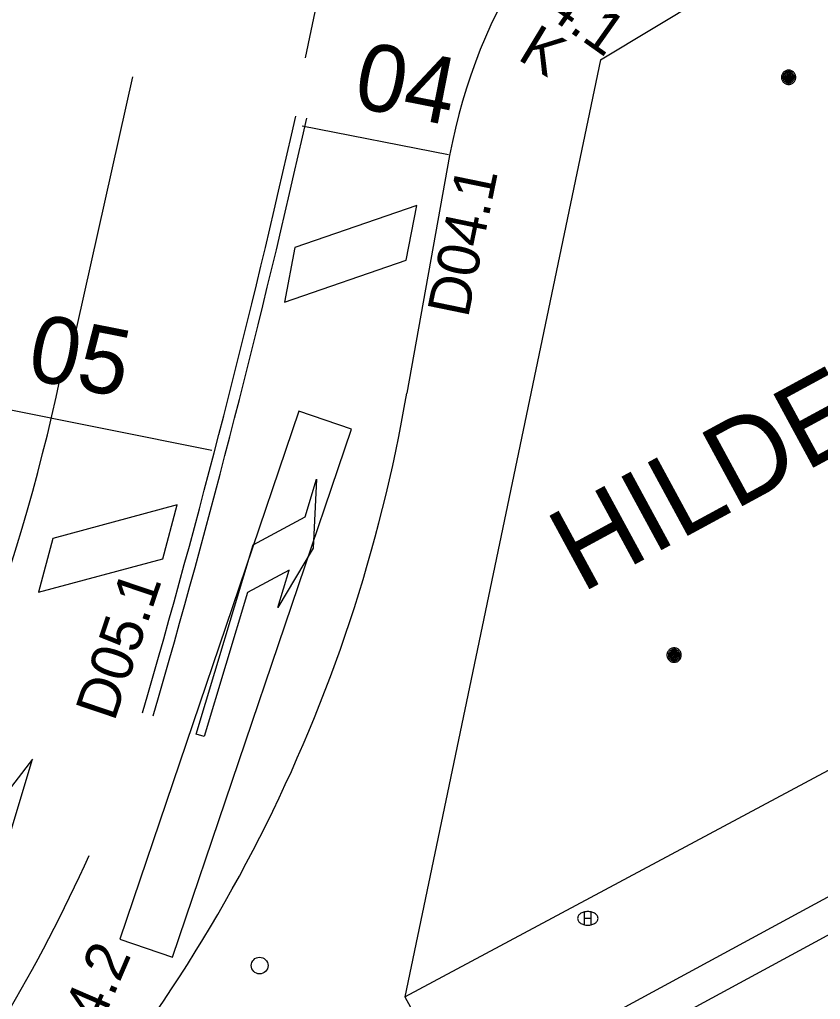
# Model space of a CAD drawing. Extents: x 81065 to 81486, y 452384 to 452681.
# Drawn here: x 81225.4 to 81239.76, y 452493.67 to 452511.24 of the extents above; entities that cross this region are included whole.
import ezdxf

# ---------------------------------------------------------------- set-up
doc = ezdxf.new("R2010")
doc.units = 0
for name, color, linetype in [('B-BH-AL-TOPOGRAFIE_STRAATNAAM-S', 7, 'Continuous'), ('B-BH-GR-BOOM-S', 7, 'Continuous'), ('B-BH-IE-MEUBILAIR_WEGMEUBILAIR_PAAL-S', 7, 'Continuous'), ('B-BH-VH-KANTOPSLUITING-GV', 7, 'Continuous'), ('B-BH-VW-HALTEPAAL-S', 7, 'Continuous'), ('B-SB-OG-WEG_SPOOR_TRAM-G', 7, 'Continuous'), ('B-WE-VW-MARKERING_DWARS_STOPSTREEP_030-G', 7, 'Continuous'), ('B-WE-VW-MARKERING_LANGS_STREEP_11_010-G', 7, 'Continuous'), ('B-WE-VW-MARKERING_LANGS_STREEP_13_010-G', 7, 'Continuous'), ('B-WE-VW-MARKERING_LANGS_STREEP_13_030-G', 7, 'Continuous'), ('B-WE-VW-MARKERING_LANGS_STREEP_DOORGETROKKEN_010-G', 7, 'Continuous'), ('B-WE-VW-MARKERING_PIJL-S', 7, 'Continuous'), ('N-OI-KL-VRI_LUS_DETECTIE-G', 7, 'Continuous'), ('N-OI-KL-VRI_LUS_DETECTIE-T18', 7, 'Continuous'), ('N-WE-VW-VRI_ARMATUUR-S', 7, 'Continuous'), ('N-WE-VW-VRI_ARMATUUR-T18', 7, 'Continuous'), ('N-WE-VW-VRI_RICHTINGNUMMER-T25', 7, 'Continuous')]:
    doc.layers.add(name, color=color, linetype=linetype)

msp = doc.modelspace()

# ---------------------------------------------------------------- linework, layer by layer
at = {"layer": 'B-BH-GR-BOOM-S'}
for points in [[(81239.065, 452510.205), (81239.066, 452510.191), (81239.068, 452510.178), (81239.071, 452510.165), (81239.076, 452510.153), (81239.082, 452510.141), (81239.09, 452510.129), (81239.098, 452510.119), (81239.108, 452510.109), (81239.118, 452510.101), (81239.13, 452510.093), (81239.142, 452510.087), (81239.154, 452510.082), (81239.167, 452510.079), (81239.18, 452510.077), (81239.194, 452510.076), (81239.207, 452510.077), (81239.221, 452510.079), (81239.234, 452510.082), (81239.246, 452510.087), (81239.258, 452510.093), (81239.27, 452510.101), (81239.28, 452510.109), (81239.29, 452510.119), (81239.298, 452510.129), (81239.306, 452510.141), (81239.312, 452510.153), (81239.316, 452510.165), (81239.32, 452510.178), (81239.322, 452510.191), (81239.323, 452510.205), (81239.322, 452510.218), (81239.32, 452510.232), (81239.316, 452510.245), (81239.312, 452510.257), (81239.306, 452510.269), (81239.298, 452510.281), (81239.29, 452510.291), (81239.28, 452510.301), (81239.27, 452510.309), (81239.258, 452510.317), (81239.246, 452510.323), (81239.234, 452510.327), (81239.221, 452510.331), (81239.207, 452510.333), (81239.194, 452510.334), (81239.18, 452510.333), (81239.167, 452510.331), (81239.154, 452510.327), (81239.142, 452510.323), (81239.13, 452510.317), (81239.118, 452510.309), (81239.108, 452510.301), (81239.098, 452510.291), (81239.09, 452510.281), (81239.082, 452510.269), (81239.076, 452510.257), (81239.071, 452510.245), (81239.068, 452510.232), (81239.066, 452510.218), (81239.065, 452510.205)], [(81239.09, 452510.205), (81239.09, 452510.194), (81239.092, 452510.183), (81239.095, 452510.173), (81239.099, 452510.162), (81239.103, 452510.153), (81239.109, 452510.144), (81239.116, 452510.135), (81239.124, 452510.127), (81239.133, 452510.12), (81239.142, 452510.114), (81239.151, 452510.11), (81239.162, 452510.106), (81239.172, 452510.103), (81239.183, 452510.101), (81239.194, 452510.101), (81239.205, 452510.101), (81239.216, 452510.103), (81239.226, 452510.106), (81239.236, 452510.11), (81239.246, 452510.114), (81239.255, 452510.12), (81239.264, 452510.127), (81239.272, 452510.135), (81239.278, 452510.144), (81239.284, 452510.153), (81239.289, 452510.162), (81239.293, 452510.173), (81239.296, 452510.183), (81239.298, 452510.194), (81239.298, 452510.205), (81239.298, 452510.216), (81239.296, 452510.227), (81239.293, 452510.237), (81239.289, 452510.247), (81239.284, 452510.257), (81239.278, 452510.266), (81239.272, 452510.275), (81239.264, 452510.283), (81239.255, 452510.289), (81239.246, 452510.295), (81239.236, 452510.3), (81239.226, 452510.304), (81239.216, 452510.307), (81239.205, 452510.309), (81239.194, 452510.309), (81239.183, 452510.309), (81239.172, 452510.307), (81239.162, 452510.304), (81239.151, 452510.3), (81239.142, 452510.295), (81239.133, 452510.289), (81239.124, 452510.283), (81239.116, 452510.275), (81239.109, 452510.266), (81239.103, 452510.257), (81239.099, 452510.247), (81239.095, 452510.237), (81239.092, 452510.227), (81239.09, 452510.216), (81239.09, 452510.205)], [(81239.112, 452510.205), (81239.113, 452510.196), (81239.114, 452510.188), (81239.116, 452510.18), (81239.119, 452510.172), (81239.123, 452510.164), (81239.128, 452510.157), (81239.133, 452510.15), (81239.139, 452510.144), (81239.146, 452510.139), (81239.153, 452510.134), (81239.161, 452510.13), (81239.169, 452510.127), (81239.177, 452510.125), (81239.185, 452510.124), (81239.194, 452510.123), (81239.202, 452510.124), (81239.211, 452510.125), (81239.219, 452510.127), (81239.227, 452510.13), (81239.235, 452510.134), (81239.242, 452510.139), (81239.249, 452510.144), (81239.255, 452510.15), (81239.26, 452510.157), (81239.265, 452510.164), (81239.268, 452510.172), (81239.272, 452510.18), (81239.274, 452510.188), (81239.275, 452510.196), (81239.276, 452510.205), (81239.275, 452510.213), (81239.274, 452510.222), (81239.272, 452510.23), (81239.268, 452510.238), (81239.265, 452510.246), (81239.26, 452510.253), (81239.255, 452510.26), (81239.249, 452510.266), (81239.242, 452510.271), (81239.235, 452510.276), (81239.227, 452510.279), (81239.219, 452510.283), (81239.211, 452510.285), (81239.202, 452510.286), (81239.194, 452510.287), (81239.185, 452510.286), (81239.177, 452510.285), (81239.169, 452510.283), (81239.161, 452510.279), (81239.153, 452510.276), (81239.146, 452510.271), (81239.139, 452510.266), (81239.133, 452510.26), (81239.128, 452510.253), (81239.123, 452510.246), (81239.119, 452510.238), (81239.116, 452510.23), (81239.114, 452510.222), (81239.113, 452510.213), (81239.112, 452510.205)], [(81239.135, 452510.205), (81239.136, 452510.199), (81239.137, 452510.193), (81239.138, 452510.187), (81239.14, 452510.181), (81239.143, 452510.176), (81239.147, 452510.17), (81239.15, 452510.166), (81239.155, 452510.161), (81239.159, 452510.158), (81239.165, 452510.154), (81239.17, 452510.151), (81239.176, 452510.149), (81239.182, 452510.148), (81239.188, 452510.147), (81239.194, 452510.146), (81239.2, 452510.147), (81239.206, 452510.148), (81239.212, 452510.149), (81239.218, 452510.151), (81239.223, 452510.154), (81239.228, 452510.158), (81239.233, 452510.161), (81239.238, 452510.166), (81239.241, 452510.17), (81239.245, 452510.176), (81239.248, 452510.181), (81239.25, 452510.187), (81239.251, 452510.193), (81239.252, 452510.199), (81239.253, 452510.205), (81239.252, 452510.211), (81239.251, 452510.217), (81239.25, 452510.223), (81239.248, 452510.229), (81239.245, 452510.234), (81239.241, 452510.239), (81239.238, 452510.244), (81239.233, 452510.249), (81239.228, 452510.252), (81239.223, 452510.256), (81239.218, 452510.259), (81239.212, 452510.261), (81239.206, 452510.262), (81239.2, 452510.263), (81239.194, 452510.264), (81239.188, 452510.263), (81239.182, 452510.262), (81239.176, 452510.261), (81239.17, 452510.259), (81239.165, 452510.256), (81239.159, 452510.252), (81239.155, 452510.249), (81239.15, 452510.244), (81239.147, 452510.239), (81239.143, 452510.234), (81239.14, 452510.229), (81239.138, 452510.223), (81239.137, 452510.217), (81239.136, 452510.211), (81239.135, 452510.205)], [(81239.158, 452510.205), (81239.158, 452510.201), (81239.159, 452510.198), (81239.16, 452510.194), (81239.161, 452510.19), (81239.163, 452510.187), (81239.165, 452510.184), (81239.167, 452510.181), (81239.17, 452510.178), (81239.173, 452510.176), (81239.176, 452510.174), (81239.179, 452510.172), (81239.183, 452510.171), (81239.187, 452510.17), (81239.19, 452510.169), (81239.194, 452510.169), (81239.198, 452510.169), (81239.201, 452510.17), (81239.205, 452510.171), (81239.209, 452510.172), (81239.212, 452510.174), (81239.215, 452510.176), (81239.218, 452510.178), (81239.22, 452510.181), (81239.223, 452510.184), (81239.225, 452510.187), (81239.227, 452510.19), (81239.228, 452510.194), (81239.229, 452510.198), (81239.23, 452510.201), (81239.23, 452510.205), (81239.23, 452510.209), (81239.229, 452510.212), (81239.228, 452510.216), (81239.227, 452510.22), (81239.225, 452510.223), (81239.223, 452510.226), (81239.22, 452510.229), (81239.218, 452510.231), (81239.215, 452510.234), (81239.212, 452510.236), (81239.209, 452510.238), (81239.205, 452510.239), (81239.201, 452510.24), (81239.198, 452510.241), (81239.194, 452510.241), (81239.19, 452510.241), (81239.187, 452510.24), (81239.183, 452510.239), (81239.179, 452510.238), (81239.176, 452510.236), (81239.173, 452510.234), (81239.17, 452510.231), (81239.167, 452510.229), (81239.165, 452510.226), (81239.163, 452510.223), (81239.161, 452510.22), (81239.16, 452510.216), (81239.159, 452510.212), (81239.158, 452510.209), (81239.158, 452510.205)], [(81239.181, 452510.205), (81239.181, 452510.204), (81239.181, 452510.202), (81239.182, 452510.201), (81239.182, 452510.2), (81239.183, 452510.199), (81239.184, 452510.197), (81239.184, 452510.196), (81239.185, 452510.195), (81239.186, 452510.195), (81239.188, 452510.194), (81239.189, 452510.193), (81239.19, 452510.193), (81239.191, 452510.192), (81239.193, 452510.192), (81239.194, 452510.192), (81239.195, 452510.192), (81239.197, 452510.192), (81239.198, 452510.193), (81239.199, 452510.193), (81239.2, 452510.194), (81239.202, 452510.195), (81239.203, 452510.195), (81239.204, 452510.196), (81239.204, 452510.197), (81239.205, 452510.199), (81239.206, 452510.2), (81239.206, 452510.201), (81239.207, 452510.202), (81239.207, 452510.204), (81239.207, 452510.205), (81239.207, 452510.206), (81239.207, 452510.208), (81239.206, 452510.209), (81239.206, 452510.21), (81239.205, 452510.211), (81239.204, 452510.213), (81239.204, 452510.214), (81239.203, 452510.215), (81239.202, 452510.215), (81239.2, 452510.216), (81239.199, 452510.217), (81239.198, 452510.217), (81239.197, 452510.218), (81239.195, 452510.218), (81239.194, 452510.218), (81239.193, 452510.218), (81239.191, 452510.218), (81239.19, 452510.217), (81239.189, 452510.217), (81239.188, 452510.216), (81239.186, 452510.215), (81239.185, 452510.215), (81239.184, 452510.214), (81239.184, 452510.213), (81239.183, 452510.211), (81239.182, 452510.21), (81239.182, 452510.209), (81239.181, 452510.208), (81239.181, 452510.206), (81239.181, 452510.205)], [(81237.011, 452499.841), (81237.012, 452499.827), (81237.014, 452499.814), (81237.017, 452499.801), (81237.022, 452499.789), (81237.028, 452499.777), (81237.036, 452499.765), (81237.044, 452499.755), (81237.054, 452499.745), (81237.064, 452499.737), (81237.076, 452499.729), (81237.088, 452499.723), (81237.1, 452499.718), (81237.113, 452499.715), (81237.126, 452499.713), (81237.14, 452499.712), (81237.153, 452499.713), (81237.167, 452499.715), (81237.18, 452499.718), (81237.192, 452499.723), (81237.204, 452499.729), (81237.216, 452499.737), (81237.226, 452499.745), (81237.236, 452499.755), (81237.244, 452499.765), (81237.252, 452499.777), (81237.258, 452499.789), (81237.262, 452499.801), (81237.266, 452499.814), (81237.268, 452499.827), (81237.269, 452499.841), (81237.268, 452499.854), (81237.266, 452499.868), (81237.262, 452499.881), (81237.258, 452499.893), (81237.252, 452499.905), (81237.244, 452499.917), (81237.236, 452499.927), (81237.226, 452499.937), (81237.216, 452499.945), (81237.204, 452499.953), (81237.192, 452499.959), (81237.18, 452499.963), (81237.167, 452499.967), (81237.153, 452499.969), (81237.14, 452499.97), (81237.126, 452499.969), (81237.113, 452499.967), (81237.1, 452499.963), (81237.088, 452499.959), (81237.076, 452499.953), (81237.064, 452499.945), (81237.054, 452499.937), (81237.044, 452499.927), (81237.036, 452499.917), (81237.028, 452499.905), (81237.022, 452499.893), (81237.017, 452499.881), (81237.014, 452499.868), (81237.012, 452499.854), (81237.011, 452499.841)], [(81237.036, 452499.841), (81237.036, 452499.83), (81237.038, 452499.819), (81237.041, 452499.809), (81237.045, 452499.798), (81237.049, 452499.789), (81237.055, 452499.78), (81237.062, 452499.771), (81237.07, 452499.763), (81237.079, 452499.756), (81237.088, 452499.75), (81237.097, 452499.746), (81237.108, 452499.742), (81237.118, 452499.739), (81237.129, 452499.737), (81237.14, 452499.737), (81237.151, 452499.737), (81237.162, 452499.739), (81237.172, 452499.742), (81237.182, 452499.746), (81237.192, 452499.75), (81237.201, 452499.756), (81237.21, 452499.763), (81237.218, 452499.771), (81237.224, 452499.78), (81237.23, 452499.789), (81237.235, 452499.798), (81237.239, 452499.809), (81237.242, 452499.819), (81237.244, 452499.83), (81237.244, 452499.841), (81237.244, 452499.852), (81237.242, 452499.863), (81237.239, 452499.873), (81237.235, 452499.883), (81237.23, 452499.893), (81237.224, 452499.902), (81237.218, 452499.911), (81237.21, 452499.919), (81237.201, 452499.925), (81237.192, 452499.931), (81237.182, 452499.936), (81237.172, 452499.94), (81237.162, 452499.943), (81237.151, 452499.945), (81237.14, 452499.945), (81237.129, 452499.945), (81237.118, 452499.943), (81237.108, 452499.94), (81237.097, 452499.936), (81237.088, 452499.931), (81237.079, 452499.925), (81237.07, 452499.919), (81237.062, 452499.911), (81237.055, 452499.902), (81237.049, 452499.893), (81237.045, 452499.883), (81237.041, 452499.873), (81237.038, 452499.863), (81237.036, 452499.852), (81237.036, 452499.841)], [(81237.058, 452499.841), (81237.059, 452499.832), (81237.06, 452499.824), (81237.062, 452499.816), (81237.065, 452499.808), (81237.069, 452499.8), (81237.074, 452499.793), (81237.079, 452499.786), (81237.085, 452499.78), (81237.092, 452499.775), (81237.099, 452499.77), (81237.107, 452499.766), (81237.115, 452499.763), (81237.123, 452499.761), (81237.131, 452499.76), (81237.14, 452499.759), (81237.148, 452499.76), (81237.157, 452499.761), (81237.165, 452499.763), (81237.173, 452499.766), (81237.181, 452499.77), (81237.188, 452499.775), (81237.195, 452499.78), (81237.201, 452499.786), (81237.206, 452499.793), (81237.211, 452499.8), (81237.214, 452499.808), (81237.218, 452499.816), (81237.22, 452499.824), (81237.221, 452499.832), (81237.222, 452499.841), (81237.221, 452499.849), (81237.22, 452499.858), (81237.218, 452499.866), (81237.214, 452499.874), (81237.211, 452499.882), (81237.206, 452499.889), (81237.201, 452499.896), (81237.195, 452499.902), (81237.188, 452499.907), (81237.181, 452499.912), (81237.173, 452499.915), (81237.165, 452499.919), (81237.157, 452499.921), (81237.148, 452499.922), (81237.14, 452499.923), (81237.131, 452499.922), (81237.123, 452499.921), (81237.115, 452499.919), (81237.107, 452499.915), (81237.099, 452499.912), (81237.092, 452499.907), (81237.085, 452499.902), (81237.079, 452499.896), (81237.074, 452499.889), (81237.069, 452499.882), (81237.065, 452499.874), (81237.062, 452499.866), (81237.06, 452499.858), (81237.059, 452499.849), (81237.058, 452499.841)], [(81237.081, 452499.841), (81237.082, 452499.835), (81237.083, 452499.829), (81237.084, 452499.823), (81237.086, 452499.817), (81237.089, 452499.812), (81237.093, 452499.806), (81237.096, 452499.802), (81237.101, 452499.797), (81237.105, 452499.794), (81237.111, 452499.79), (81237.116, 452499.787), (81237.122, 452499.785), (81237.128, 452499.784), (81237.134, 452499.783), (81237.14, 452499.782), (81237.146, 452499.783), (81237.152, 452499.784), (81237.158, 452499.785), (81237.164, 452499.787), (81237.169, 452499.79), (81237.174, 452499.794), (81237.179, 452499.797), (81237.184, 452499.802), (81237.187, 452499.806), (81237.191, 452499.812), (81237.194, 452499.817), (81237.196, 452499.823), (81237.197, 452499.829), (81237.198, 452499.835), (81237.199, 452499.841), (81237.198, 452499.847), (81237.197, 452499.853), (81237.196, 452499.859), (81237.194, 452499.865), (81237.191, 452499.87), (81237.187, 452499.875), (81237.184, 452499.88), (81237.179, 452499.885), (81237.174, 452499.888), (81237.169, 452499.892), (81237.164, 452499.895), (81237.158, 452499.897), (81237.152, 452499.898), (81237.146, 452499.899), (81237.14, 452499.9), (81237.134, 452499.899), (81237.128, 452499.898), (81237.122, 452499.897), (81237.116, 452499.895), (81237.111, 452499.892), (81237.105, 452499.888), (81237.101, 452499.885), (81237.096, 452499.88), (81237.093, 452499.875), (81237.089, 452499.87), (81237.086, 452499.865), (81237.084, 452499.859), (81237.083, 452499.853), (81237.082, 452499.847), (81237.081, 452499.841)], [(81237.104, 452499.841), (81237.104, 452499.837), (81237.105, 452499.834), (81237.106, 452499.83), (81237.107, 452499.826), (81237.109, 452499.823), (81237.111, 452499.82), (81237.113, 452499.817), (81237.116, 452499.814), (81237.119, 452499.812), (81237.122, 452499.81), (81237.125, 452499.808), (81237.129, 452499.807), (81237.133, 452499.806), (81237.136, 452499.805), (81237.14, 452499.805), (81237.144, 452499.805), (81237.147, 452499.806), (81237.151, 452499.807), (81237.155, 452499.808), (81237.158, 452499.81), (81237.161, 452499.812), (81237.164, 452499.814), (81237.166, 452499.817), (81237.169, 452499.82), (81237.171, 452499.823), (81237.173, 452499.826), (81237.174, 452499.83), (81237.175, 452499.834), (81237.176, 452499.837), (81237.176, 452499.841), (81237.176, 452499.845), (81237.175, 452499.848), (81237.174, 452499.852), (81237.173, 452499.856), (81237.171, 452499.859), (81237.169, 452499.862), (81237.166, 452499.865), (81237.164, 452499.867), (81237.161, 452499.87), (81237.158, 452499.872), (81237.155, 452499.874), (81237.151, 452499.875), (81237.147, 452499.876), (81237.144, 452499.877), (81237.14, 452499.877), (81237.136, 452499.877), (81237.133, 452499.876), (81237.129, 452499.875), (81237.125, 452499.874), (81237.122, 452499.872), (81237.119, 452499.87), (81237.116, 452499.867), (81237.113, 452499.865), (81237.111, 452499.862), (81237.109, 452499.859), (81237.107, 452499.856), (81237.106, 452499.852), (81237.105, 452499.848), (81237.104, 452499.845), (81237.104, 452499.841)], [(81237.127, 452499.841), (81237.127, 452499.84), (81237.127, 452499.838), (81237.128, 452499.837), (81237.128, 452499.836), (81237.129, 452499.835), (81237.13, 452499.833), (81237.13, 452499.832), (81237.131, 452499.831), (81237.132, 452499.831), (81237.134, 452499.83), (81237.135, 452499.829), (81237.136, 452499.829), (81237.137, 452499.828), (81237.139, 452499.828), (81237.14, 452499.828), (81237.141, 452499.828), (81237.143, 452499.828), (81237.144, 452499.829), (81237.145, 452499.829), (81237.146, 452499.83), (81237.148, 452499.831), (81237.149, 452499.831), (81237.15, 452499.832), (81237.15, 452499.833), (81237.151, 452499.835), (81237.152, 452499.836), (81237.152, 452499.837), (81237.153, 452499.838), (81237.153, 452499.84), (81237.153, 452499.841), (81237.153, 452499.842), (81237.153, 452499.844), (81237.152, 452499.845), (81237.152, 452499.846), (81237.151, 452499.847), (81237.15, 452499.849), (81237.15, 452499.85), (81237.149, 452499.851), (81237.148, 452499.851), (81237.146, 452499.852), (81237.145, 452499.853), (81237.144, 452499.853), (81237.143, 452499.854), (81237.141, 452499.854), (81237.14, 452499.854), (81237.139, 452499.854), (81237.137, 452499.854), (81237.136, 452499.853), (81237.135, 452499.853), (81237.134, 452499.852), (81237.132, 452499.851), (81237.131, 452499.851), (81237.13, 452499.85), (81237.13, 452499.849), (81237.129, 452499.847), (81237.128, 452499.846), (81237.128, 452499.845), (81237.127, 452499.844), (81237.127, 452499.842), (81237.127, 452499.841)]]:
    msp.add_lwpolyline(points, dxfattribs=at)
at = {"layer": 'B-BH-IE-MEUBILAIR_WEGMEUBILAIR_PAAL-S'}
msp.add_circle((81229.705, 452494.272), 0.15, dxfattribs=at)
at = {"layer": 'B-BH-VH-KANTOPSLUITING-GV'}
for p, q in [((81235.82, 452510.52), (81241.105, 452513.698)), ((81232.312, 452493.712), (81264.058, 452510.715)), ((81235.82, 452510.52), (81232.312, 452493.712)), ((81233.113, 452508.803), (81232.345, 452504.541)), ((81233.291, 452491.927), (81250, 452500.979))]:
    msp.add_line(p, q, dxfattribs=at)
msp.add_lwpolyline([(81232.312, 452493.712), (81233.291, 452491.927)], dxfattribs=at)
for centre, radius, start, end in [((81242.762, 452507.028), 9.811, 80.0525, 169.5766), ((81204.782, 452509.244), 27.961, 315.7914, 350.3166)]:
    msp.add_arc(centre, radius, start, end, dxfattribs=at)
at = {"layer": 'B-BH-VW-HALTEPAAL-S'}
for p, q in [((81235.531, 452495.004), (81235.531, 452495.234)), ((81235.653, 452495.004), (81235.653, 452495.234)), ((81235.653, 452495.119), (81235.531, 452495.119))]:
    msp.add_line(p, q, dxfattribs=at)
msp.add_lwpolyline([(81235.409, 452495.119), (81235.41, 452495.106), (81235.413, 452495.093), (81235.418, 452495.081), (81235.425, 452495.069), (81235.433, 452495.058), (81235.444, 452495.047), (81235.456, 452495.037), (81235.469, 452495.028), (81235.484, 452495.02), (81235.5, 452495.013), (81235.517, 452495.007), (81235.535, 452495.003), (81235.554, 452494.999), (81235.573, 452494.998), (81235.592, 452494.997), (81235.611, 452494.998), (81235.63, 452494.999), (81235.649, 452495.003), (81235.666, 452495.007), (81235.683, 452495.013), (81235.7, 452495.02), (81235.714, 452495.028), (81235.728, 452495.037), (81235.74, 452495.047), (81235.75, 452495.058), (81235.759, 452495.069), (81235.766, 452495.081), (81235.771, 452495.093), (81235.774, 452495.106), (81235.775, 452495.119), (81235.774, 452495.132), (81235.771, 452495.144), (81235.766, 452495.157), (81235.759, 452495.169), (81235.75, 452495.18), (81235.74, 452495.191), (81235.728, 452495.201), (81235.714, 452495.21), (81235.7, 452495.218), (81235.683, 452495.225), (81235.666, 452495.23), (81235.649, 452495.235), (81235.63, 452495.238), (81235.611, 452495.24), (81235.592, 452495.241), (81235.573, 452495.24), (81235.554, 452495.238), (81235.535, 452495.235), (81235.517, 452495.23), (81235.5, 452495.225), (81235.484, 452495.218), (81235.469, 452495.21), (81235.456, 452495.201), (81235.444, 452495.191), (81235.433, 452495.18), (81235.425, 452495.169), (81235.418, 452495.157), (81235.413, 452495.144), (81235.41, 452495.132), (81235.409, 452495.119)], dxfattribs=at)
at = {"layer": 'B-SB-OG-WEG_SPOOR_TRAM-G'}
msp.add_line((81250, 452500.286), (81195.496, 452470.783), dxfattribs=at)
at = {"layer": 'B-WE-VW-MARKERING_DWARS_STOPSTREEP_030-G'}
for p, q in [((81230.47, 452509.335), (81233.095, 452508.818)), ((81223.002, 452504.688), (81228.847, 452503.514))]:
    msp.add_line(p, q, dxfattribs=at)
at = {"layer": 'B-WE-VW-MARKERING_LANGS_STREEP_11_010-G'}
msp.add_line((81230.53, 452510.556), (81233.127, 452523.076), dxfattribs=at)
at = {"layer": 'B-WE-VW-MARKERING_LANGS_STREEP_13_010-G'}
msp.add_line((81227.422, 452510.211), (81226.305, 452505.208), dxfattribs=at)
msp.add_arc((81191.876, 452512.085), 35.017, 329.8334, 348.0069, dxfattribs=at)
at = {"layer": 'B-WE-VW-MARKERING_LANGS_STREEP_13_030-G'}
msp.add_arc((81200.266, 452508.145), 28.94, 309.535, 335.7286, dxfattribs=at)
at = {"layer": 'B-WE-VW-MARKERING_LANGS_STREEP_DOORGETROKKEN_010-G'}
for radius, end in [(179.327, 347.35651), (179.527, 347.35932)]:
    msp.add_arc((81055.375, 452548.758), radius, 343.8259, end, dxfattribs=at)
at = {"layer": 'B-WE-VW-MARKERING_PIJL-S'}
for p, q in [((81230.524, 452502.322), (81230.726, 452502.994)), ((81230.726, 452502.994), (81230.667, 452501.757)), ((81229.589, 452501.821), (81230.524, 452502.322)), ((81228.565, 452498.421), (81229.589, 452501.821)), ((81230.667, 452501.757), (81230.034, 452500.695)), ((81230.235, 452501.366), (81229.488, 452500.964)), ((81230.034, 452500.695), (81230.235, 452501.366)), ((81229.488, 452500.964), (81228.708, 452498.379)), ((81228.708, 452498.379), (81228.565, 452498.421))]:
    msp.add_line(p, q, dxfattribs=at)
msp.add_lwpolyline([(81225.631, 452497.977), (81224.359, 452496.327), (81224.625, 452496.19), (81223.273, 452493.568), (81223.407, 452493.499), (81224.758, 452496.121), (81225.025, 452495.984)], close=True, dxfattribs=at)
at = {"layer": 'N-OI-KL-VRI_LUS_DETECTIE-G'}
for p, q in [((81232.522, 452507.904), (81230.339, 452507.152)), ((81232.332, 452506.922), (81232.522, 452507.904)), ((81230.339, 452507.152), (81230.148, 452506.172)), ((81230.148, 452506.172), (81232.332, 452506.922)), ((81230.407, 452504.215), (81227.197, 452494.745)), ((81231.354, 452503.896), (81230.407, 452504.215)), ((81228.144, 452494.426), (81231.354, 452503.896)), ((81228.224, 452502.536), (81225.995, 452501.934)), ((81227.968, 452501.57), (81228.224, 452502.536)), ((81225.995, 452501.934), (81225.738, 452500.969)), ((81225.738, 452500.969), (81227.968, 452501.57)), ((81227.197, 452494.745), (81228.144, 452494.426))]:
    msp.add_line(p, q, dxfattribs=at)

# ---------------------------------------------------------------- texts
at = {"layer": 'B-BH-AL-TOPOGRAFIE_STRAATNAAM-S'}
msp.add_text('HILDEBRANDPLEIN', height=1.5, rotation=28.4741, dxfattribs=at).set_placement((81235.475, 452500.944))
at = {"layer": 'N-OI-KL-VRI_LUS_DETECTIE-T18'}
for s, rotation, p in [('D04.1', 78.3917, (81233.441, 452505.873)), ('D05.1', 71.3675, (81227.097, 452498.634)), ('D04.2', 66.6069, (81226.347, 452492.01))]:
    msp.add_text(s, height=0.75, rotation=rotation, dxfattribs=at).set_placement(p)
at = {"layer": 'N-WE-VW-VRI_ARMATUUR-S'}
msp.add_text('K', height=0.75, rotation=328.8738, dxfattribs=at).set_placement((81234.31, 452510.537))
at = {"layer": 'N-WE-VW-VRI_ARMATUUR-T18'}
msp.add_text('04.1', height=0.75, rotation=324.7531, dxfattribs=at).set_placement((81234.32, 452511.682))
at = {"layer": 'N-WE-VW-VRI_RICHTINGNUMMER-T25'}
for s, p in [('04', (81231.349, 452509.682)), ('05', (81225.495, 452504.802))]:
    msp.add_text(s, height=1.2, rotation=348.8664, dxfattribs=at).set_placement(p)

doc.saveas('drawing.dxf')
